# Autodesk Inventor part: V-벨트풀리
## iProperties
Company: 한국ATC센터
Created: 2014-07
Part Number: V-벨트풀리
Document SubType Name: Modeling
Designer: KYOUNG IL JANG
Density: 2.71 g/cm^3
Material: 알루미늄-6061
Mass: 204.452 g
Surface Area: 234.113 cm^2
Volume: 75.4437 cm^3
Author: KYOUNG IL JANG
